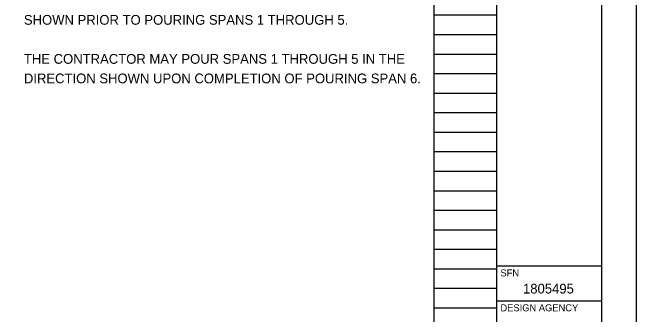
# Model space of a CAD drawing. Extents: x 0 to 34, y 0 to 22.
# Drawn here: x 25.06 to 34, y 4.8 to 9.14 of the extents above; entities that cross this region are included whole.
import ezdxf

# ---------------------------------------------------------------- set-up
doc = ezdxf.new("R2010")
doc.units = 0
for name, color, linetype in [('BR_P_Gen_Text', 7, 'Continuous'), ('SH_Border', 7, 'Continuous'), ('SH_Cut_Line', 7, 'Continuous'), ('SH_Data', 7, 'Continuous')]:
    doc.layers.add(name, color=color, linetype=linetype)

msp = doc.modelspace()

# ---------------------------------------------------------------- linework, layer by layer
at = {"layer": 'SH_Border'}
for p, q in [((32, 0.5), (32, 21.5)), ((32, 5.5), (33.5, 5.5)), ((32, 5), (33.5, 5))]:
    msp.add_line(p, q, dxfattribs=at)
msp.add_lwpolyline([(1.5, 21.5), (33.5, 21.5), (33.5, 0.5), (1.5, 0.5)], close=True, dxfattribs=at)
at = {"layer": 'SH_Cut_Line'}
msp.add_lwpolyline([(0, 0), (34, 0), (34, 22), (0, 22)], close=True, dxfattribs=at)
at = {"layer": 'SH_Data'}
for p, q in [((31.1, 0.98), (31.1, 21.14)), ((32, 0.98), (32, 21.14)), ((31.1, 9.1), (32, 9.1)), ((31.1, 8.82), (32, 8.82)), ((31.1, 8.54), (32, 8.54)), ((31.1, 8.26), (32, 8.26)), ((31.1, 7.98), (32, 7.98)), ((31.1, 7.7), (32, 7.7)), ((31.1, 7.42), (32, 7.42)), ((31.1, 7.14), (32, 7.14)), ((31.1, 6.86), (32, 6.86)), ((31.1, 6.58), (32, 6.58)), ((31.1, 6.3), (32, 6.3)), ((31.1, 6.02), (32, 6.02)), ((31.1, 5.74), (32, 5.74)), ((31.1, 5.46), (32, 5.46)), ((31.1, 5.18), (32, 5.18)), ((31.1, 4.9), (32, 4.9))]:
    msp.add_line(p, q, dxfattribs=at)

# ---------------------------------------------------------------- texts
at = {"layer": 'BR_P_Gen_Text'}
for s, p in [('SHOWN PRIOR TO POURING SPANS 1 THROUGH 5.', (25.22, 8.96)), ('THE CONTRACTOR MAY POUR SPANS 1 THROUGH 5 IN THE ', (25.22, 8.4)), ('DIRECTION SHOWN UPON COMPLETION OF POURING SPAN 6.', (25.22, 8.12))]:
    msp.add_text(s, height=0.14, dxfattribs=at).set_placement(p)
at = {"layer": 'SH_Data'}
for s, height, p in [('SFN', 0.1, (32.05, 5.35)), ('1805495', 0.14, (32.3733, 5.105)), ('DESIGN AGENCY', 0.1, (32.05, 4.85))]:
    msp.add_text(s, height=height, dxfattribs=at).set_placement(p)

doc.saveas('drawing.dxf')
